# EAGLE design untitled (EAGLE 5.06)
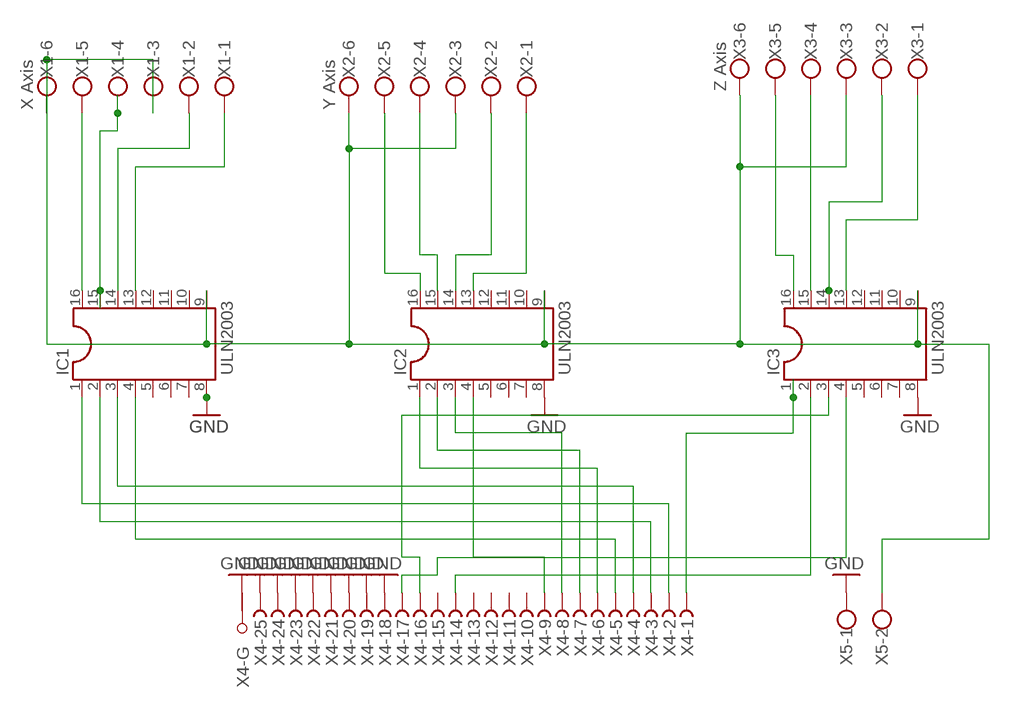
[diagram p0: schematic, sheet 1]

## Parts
IC1  ULN2003  DIL16S  [SOCKET-16]
IC2  ULN2003  DIL16S  [SOCKET-16]
IC3  ULN2003  DIL16S  [SOCKET-16]
X1  X Axis  W237-6  [W237-6]
X2  Y Axis  W237-6  [W237-6]
X3  Z Axis  W237-6  [W237-6]
X4  F25HPS  [F25HP]
X5  W237-102  [W237-102]

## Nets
GND: IC1.8 IC2.8 IC3.8 X4.18(-18:F) X4.19(-19:F) X4.20(-20:F) X4.21(-21:F) X4.22(-22:F) X4.23(-23:F) X4.24(-24:F) X4.25(-25:F) X4.G1(-G:G1) X5.1
N$1: IC1.16 X1.5
N$2: IC1.15 X1.4
N$3: IC1.14 X1.2
N$4: IC1.13 X1.1
N$5: IC1.1 X4.2(-2:F)
N$6: IC2.16 X2.5
N$7: IC2.15 X2.4
N$8: IC2.14 X2.2
N$9: IC2.13 X2.1
N$10: IC1.2 X4.3(-3:F)
N$11: IC1.9 IC2.9 IC3.9 X1.3 X1.6 X2.3 X2.6 X3.3 X3.6 X5.2
N$12: IC3.16 X3.5
N$13: IC3.15 X3.4
N$14: IC3.14 X3.2
N$15: IC3.13 X3.1
N$16: IC1.3 X4.4(-4:F)
N$17: IC1.4 X4.5(-5:F)
N$18: IC2.1 X4.6(-6:F)
N$19: IC2.2 X4.7(-7:F)
N$20: IC2.3 X4.8(-8:F)
N$21: IC2.4 X4.9(-9:F)
N$22: IC3.1 X4.1(-1:F)
N$23: IC3.2 X4.14(-14:F)
N$24: IC3.3 X4.16(-16:F)
N$25: IC3.4 X4.17(-17:F)
Unconnected: IC1.5 IC1.6 IC1.7 IC1.10 IC1.11 IC1.12 IC2.5 IC2.6 IC2.7 IC2.10 IC2.11 IC2.12 IC3.5 IC3.6 IC3.7 IC3.10 IC3.11 IC3.12 X4.10(-10:F) X4.11(-11:F) X4.12(-12:F) X4.13(-13:F) X4.15(-15:F) X4.G2(-G:G2)

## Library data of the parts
IC1-IC3 = ic-package:DIL16: Dual In Line / Socket
X1-X3 = con-wago-500:W237-6: WAGO SCREW CLAMP
X4 = con-subd:F25HPS: SUB-D
X5 = con-wago-500:W237-102: WAGO SCREW CLAMP

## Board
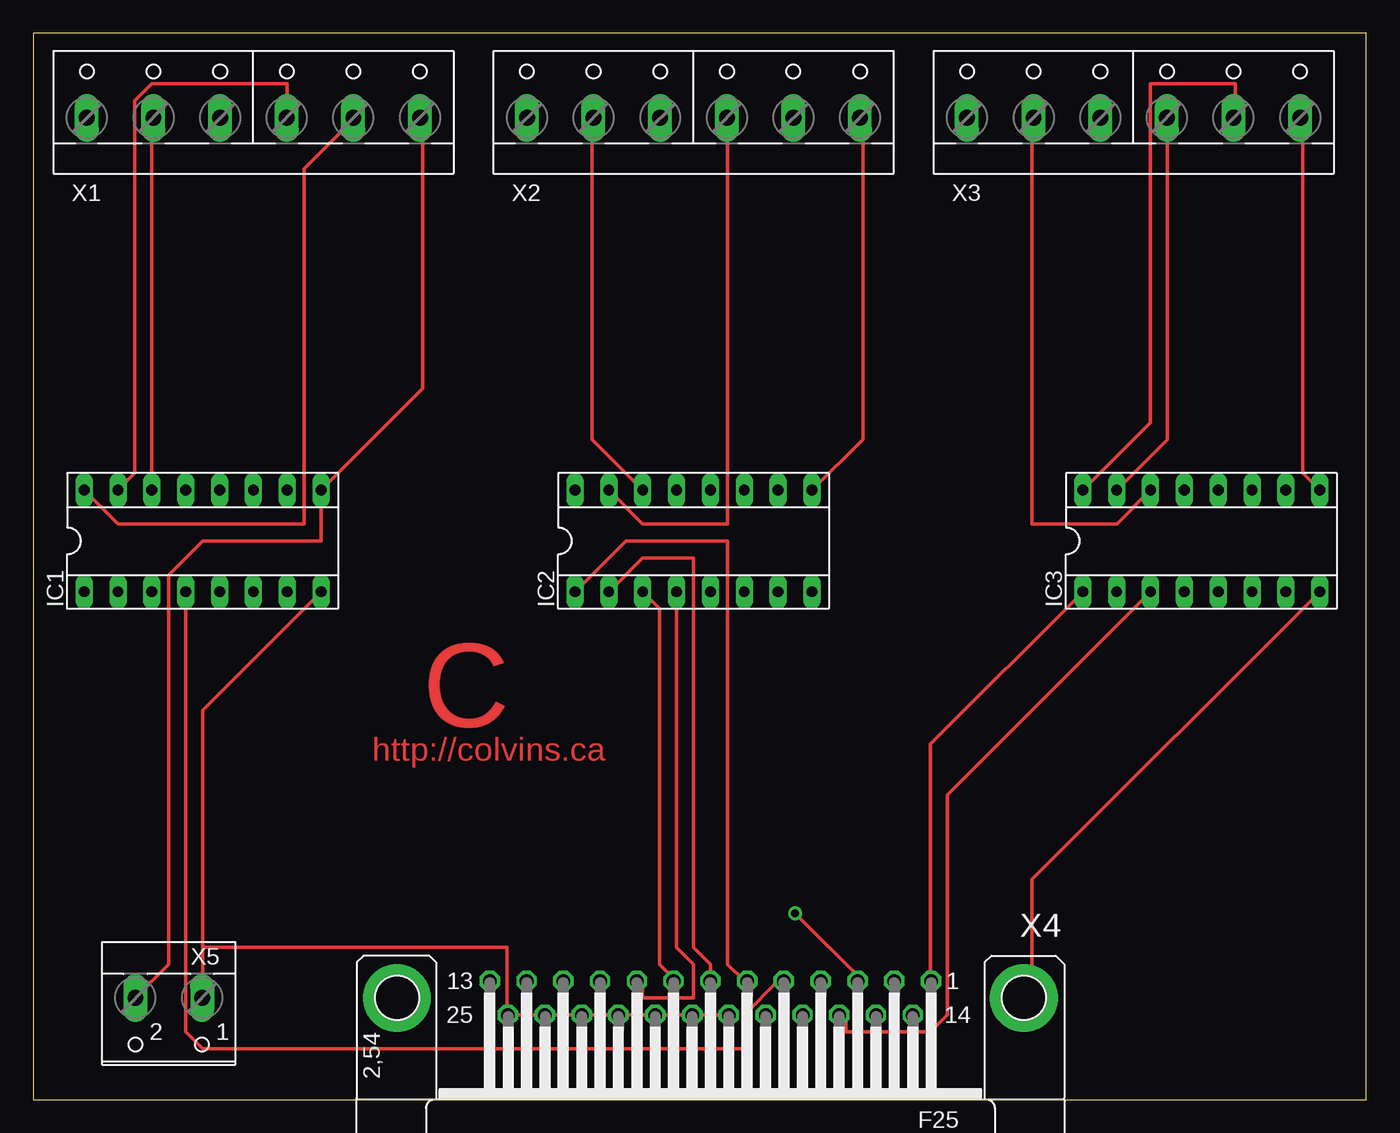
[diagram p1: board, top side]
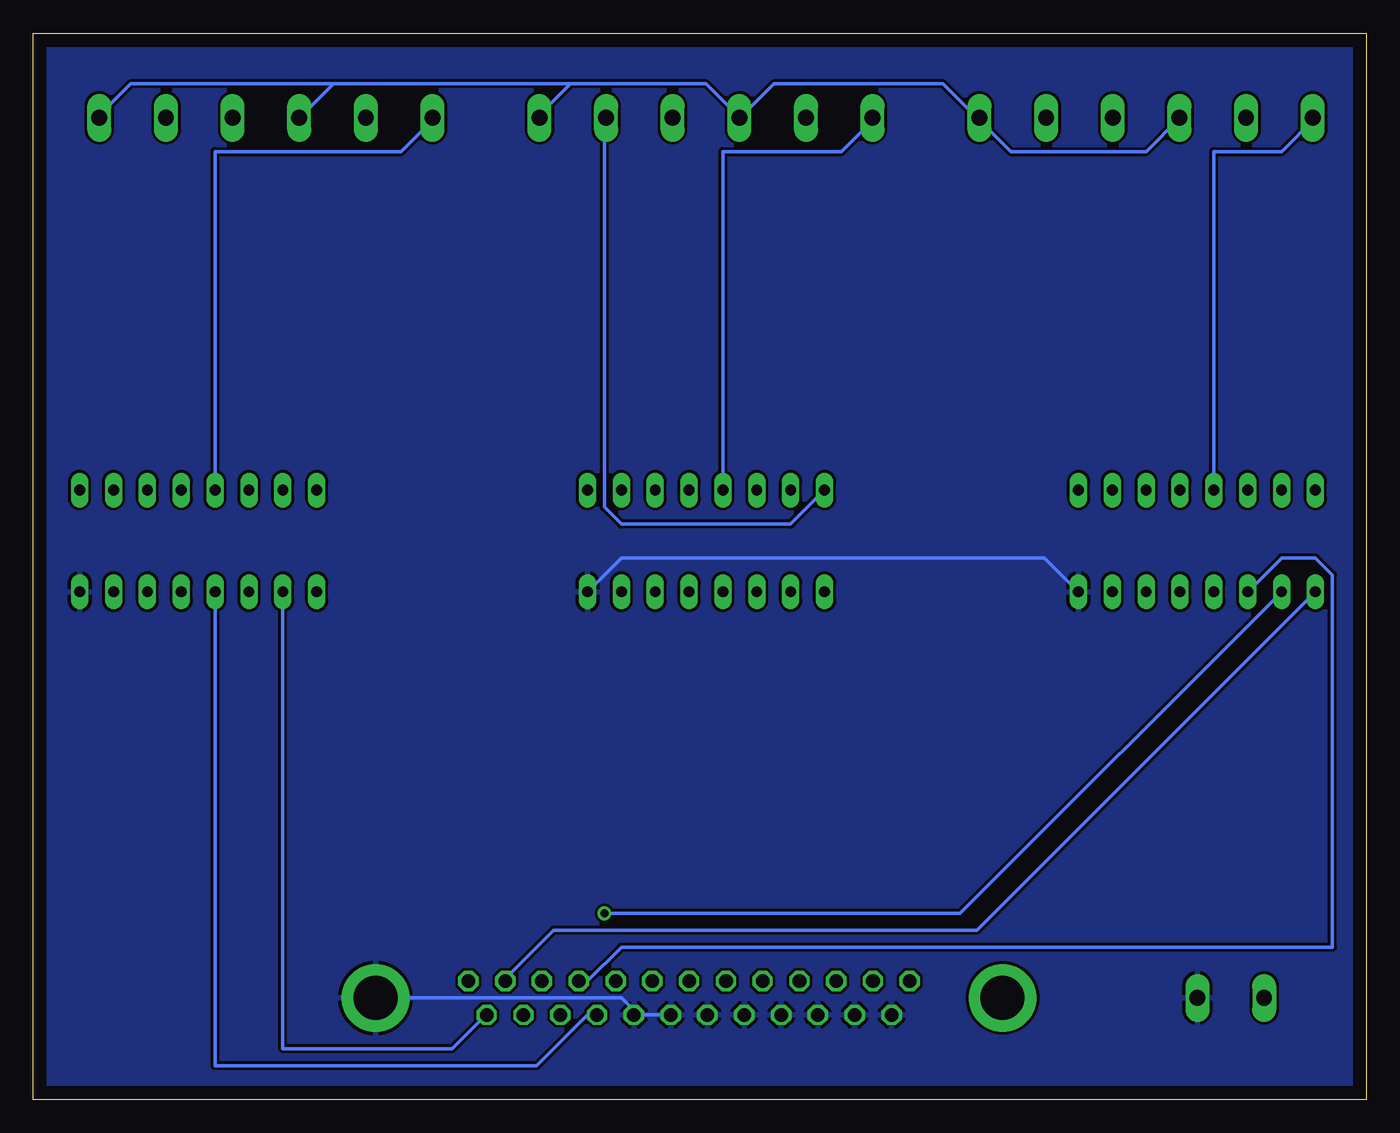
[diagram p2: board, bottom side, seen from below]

Size 100 x 80 mm. Coordinates in mm from the lower left corner, seen from the top.
Outline: 0,0 100,0 100,80 0,80 0,0
Copper layers (1*16): Top 0.035mm / dielectric 1.5mm / Bottom 0.035mm
Design rules "default": minimum track width 10mil, minimum drill 24mil, track to track 8mil, track to pad 8mil, pad to pad 8mil, via to via 8mil, smd to smd 8mil, copper to edge 40mil, drill to drill 8mil, minimum pad ring 10mil, minimum via ring 8mil, stop-mask expansion 4mil, vias tented up to drill 0mil, thermal gap 10mil

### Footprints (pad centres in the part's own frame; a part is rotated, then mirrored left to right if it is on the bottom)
SOCKET-16 = drill 0.813 long: 1 -8.89,-3.81; 2 -6.35,-3.81; 3 -3.81,-3.81; 4 -1.27,-3.81; 5 1.27,-3.81; 6 3.81,-3.81; 7 6.35,-3.81; 8 8.89,-3.81; 9 8.89,3.81; 10 6.35,3.81; 11 3.81,3.81; 12 1.27,3.81; 13 -1.27,3.81; 14 -3.81,3.81; 15 -6.35,3.81; 16 -8.89,3.81
W237-6 = drill 1.194 long: 1 -12.5,-1.27; 2 -7.5,-1.27; 3 -2.5,-1.27; 4 2.5,-1.27; 5 7.5,-1.27; 6 12.5,-1.27
F25HP = drill 1.016 octagon: 1 -16.561,-1.27; 2 -13.792,-1.27; 3 -11.049,-1.27; 4 -8.28,-1.27; 5 -5.512,-1.27; 6 -2.769,-1.27; 7 0,-1.27; 8 2.769,-1.27; 9 5.512,-1.27; 10 8.28,-1.27; 11 11.049,-1.27; 12 13.792,-1.27; 13 16.561,-1.27; 14 -15.189,1.27; 15 -12.421,1.27; 16 -9.652,1.27; 17 -6.909,1.27; 18 -4.14,1.27; 19 -1.372,1.27; 20 1.372,1.27; 21 4.14,1.27; 22 6.909,1.27; 23 9.652,1.27; 24 12.421,1.27; 25 15.189,1.27 | drill 3.302 pad 5.08 round: G1 -23.52,0; G2 23.52,0
W237-102 = drill 1.194 long: 1 -2.5,-1.27; 2 2.5,-1.27

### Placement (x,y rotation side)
IC1  12.7,41.91 0 top
IC2  49.53,41.91 0 top
IC3  87.63,41.91 0 top
X1  16.51,74.93 0 top
X2  49.53,74.93 0 top
X3  82.55,74.93 0 top
X4  50.8,7.62 180 top
X5  10.16,6.35 180 top

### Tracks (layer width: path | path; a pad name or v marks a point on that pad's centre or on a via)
GND
  Top 0.254: IC1.8 12.7,29.21 12.7,11.43 | 12.7,11.43 12.7,7.62 X5.1 | X4.19 49.53,6.35 X4.20 46.99,6.35 X4.21 X4.22 X4.23 40.64,6.35 X4.24 38.1,6.35 X4.25 35.56,6.35 35.56,11.43 12.7,11.43 | IC3.8 74.93,16.51 74.93,7.62 X4.G1
  Bottom 0.254: IC2.8 55.88,40.64 24.13,40.64 IC1.8 | 54.61,6.35 X4.19 52.07,6.35 | 54.61,6.35 55.88,7.62 X4.G1 | 54.61,6.35 X4.18
  pour Bottom: 0,80.01 100.33,80.01 100.33,-1.27 0,-1.27
N$1
  Top 0.254: IC1.16 6.35,43.18 20.32,43.18 20.32,69.85 24.13,73.66 X1.5
N$2
  Top 0.254: IC1.15 7.62,46.99 7.62,74.93 8.89,76.2 19.05,76.2 19.05,73.66 X1.4
N$3
  Top 0.254: IC1.14 8.89,73.66 X1.2
N$4
  Bottom 0.254: IC1.13 11.43,71.12 6.35,71.12 3.81,73.66 X1.1
N$5
  Bottom 0.254: IC1.1 29.21,12.7 60.96,12.7 64.77,8.89 X4.2
N$6
  Bottom 0.254: IC2.16 43.18,43.18 55.88,43.18 57.15,44.45 57.15,73.66 X2.5
N$7
  Top 0.254: IC2.15 45.72,43.18 52.07,43.18 52.07,73.66 X2.4
N$8
  Top 0.254: IC2.14 41.91,49.53 41.91,73.66 X2.2
N$9
  Bottom 0.254: IC2.13 48.26,71.12 39.37,71.12 36.83,73.66 X2.1
N$10  (via drill 0.61)
  Top 0.254: v57.15,13.97 62.23,8.89 X4.3
  Bottom 0.254: IC1.2 30.48,13.97 v57.15,13.97
N$11
  Top 0.254: IC3.9 95.25,46.99 95.25,73.66 X3.6 | IC2.9 62.23,49.53 62.23,73.66 X2.6 | X1.6 29.21,73.66 29.21,53.34 IC1.9 21.59,41.91 12.7,41.91 10.16,39.37 10.16,10.16 7.62,7.62 X5.2
  Bottom 0.254: 46.99,73.66 49.53,76.2 59.69,76.2 | 59.69,76.2 62.23,73.66 X2.6 | 77.47,76.2 80.01,73.66 X3.3 | 59.69,76.2 77.47,76.2 | 77.47,76.2 92.71,76.2 95.25,73.66 X3.6 | 29.21,73.66 26.67,71.12 16.51,71.12 13.97,73.66 X1.3 | 46.99,73.66 44.45,76.2 31.75,76.2 29.21,73.66 | 46.99,73.66 X2.3 | X1.6 29.21,73.66
N$12
  Top 0.254: IC3.16 83.82,50.8 83.82,76.2 90.17,76.2 90.17,73.66 X3.5
N$13
  Top 0.254: IC3.15 85.09,49.53 85.09,73.66 X3.4
N$14
  Top 0.254: IC3.14 81.28,43.18 74.93,43.18 74.93,73.66 X3.2
N$15
  Bottom 0.254: IC3.13 86.36,71.12 72.39,71.12 69.85,73.66 X3.1
N$16
  Bottom 0.254: IC1.3 6.35,40.64 3.81,40.64 2.54,39.37 2.54,11.43 55.88,11.43 58.42,8.89 X4.4
N$17
  Top 0.254: IC1.4 11.43,5.08 12.7,3.81 53.34,3.81 53.34,6.35 55.88,8.89 X4.5
N$18
  Top 0.254: IC2.1 44.45,41.91 52.07,41.91 52.07,10.16 53.34,8.89 X4.6
N$19
  Top 0.254: IC2.2 45.72,40.64 49.53,40.64 49.53,11.43 50.8,10.16 X4.7
N$20
  Top 0.254: IC2.3 46.99,36.83 46.99,10.16 48.26,8.89 X4.8
N$21
  Top 0.254: IC2.4 48.26,11.43 49.53,10.16 49.53,7.62 45.72,7.62 45.72,8.89 X4.9
N$22
  Top 0.254: IC3.1 67.31,26.67 67.31,8.89 X4.1
N$23
  Bottom 0.254: IC3.2 81.28,3.81 68.58,3.81 66.04,6.35 X4.14
N$24
  Top 0.254: IC3.3 68.58,22.86 68.58,6.35 67.31,5.08 60.96,5.08 60.96,6.35 X4.16
N$25
  Bottom 0.254: IC3.4 86.36,2.54 62.23,2.54 58.42,6.35 X4.17

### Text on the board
Top: C | http://colvins.ca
